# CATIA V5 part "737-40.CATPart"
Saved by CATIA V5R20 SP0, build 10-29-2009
Part number: 737-40
Definition: NONE
Nomenclature: 737-40
Source: Unknown
Description: 737-40
Bounding box of the stored display mesh (mm): x -42.5 to 33, y -42.431 to 42.431, z -47 to 30
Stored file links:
  C:\Users\Utente\Desktop\IO LAVORO\3D X SITO CF\X SITO\737\737-40.CATPart
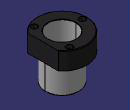
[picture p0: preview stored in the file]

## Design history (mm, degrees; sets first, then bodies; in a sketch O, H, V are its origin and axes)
Body1 "737-40" (main body)
  Solid1: solid without history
